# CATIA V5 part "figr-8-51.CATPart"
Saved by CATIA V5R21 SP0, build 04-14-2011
Part number: Part1
Bounding box of the stored display mesh (mm): x -75 to 75, y -75 to 75, z 0 to 10
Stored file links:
  D:\CATIA V5R21 E-RESOURCES\CATIA-V5R21\catia-v5r21-prt\c08-catia-v5r20-prt\c08-catia-v5r21-figr-8-51.CATPart
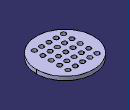
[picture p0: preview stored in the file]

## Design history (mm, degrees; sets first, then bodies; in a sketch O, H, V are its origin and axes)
Body1 (main body)
  Sketch1 on xy-plane, origin (0, 0, 0), H (1, 0, 0), V (0, 1, 0)
    circle A1 centre (0, 0) radius 75
    point P1 (0, 75)
    radius A1 = 75
    coincidence: A1 P1, P1 V
  Pad1: profile Sketch1, direction (0, 0, 1), length 10
  Sketch2 on face of Pad1, origin (0, 0, 10), H (1, 0, 0), V (0, 1, 0)
    circle A1 centre (35, -45) radius 6
    point P1 (35, -45)
    distance P1 H = 45
    distance V P1 = 35
    radius A1 = 6
  Pocket1: profile Sketch2, direction (0, 0, -1), through (limit type 3)
  RectPattern1: of Pocket1, direction 1 instances 5, spacing 19, along xy-plane reversed, direction 2 instances 5, spacing 22, along xy-plane
  Affinity1: ToTransfor RectPattern1, RatioX 1, RatioY 1, RatioZ 1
